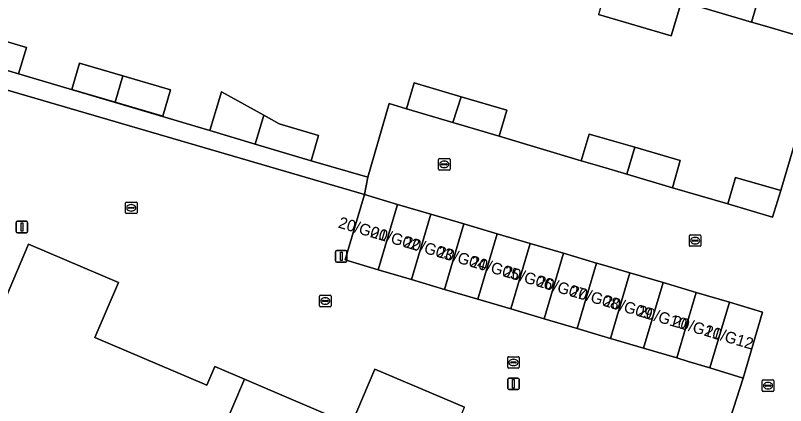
# Model space of a CAD drawing. Extents: x 161771 to 163125, y 382475 to 383179.
# Drawn here: x 162448.9 to 162516.2, y 382553 to 382587.1 of the extents above; entities that cross this region are included whole.
import ezdxf

# ---------------------------------------------------------------- set-up
doc = ezdxf.new("R2010")
doc.units = 0
for name, color, linetype in [('IMGEO_Erf', 7, 'Continuous'), ('IMGEO_Kolk', 7, 'Continuous'), ('IMGEO_Lichtmast', 7, 'Continuous'), ('IMGEO_Pand', 7, 'Continuous'), ('IMGEO_Pand_nummerreeks', 7, 'Continuous'), ('IMGEO_Voetpad_open', 7, 'Continuous')]:
    doc.layers.add(name, color=color, linetype=linetype)

msp = doc.modelspace()

# ---------------------------------------------------------------- linework, layer by layer
at = {"layer": 'IMGEO_Erf'}
for points in [[(162445.786, 382585.524), (162449.901, 382584.31), (162449.219, 382581.999), (162465.935, 382577.029), (162466.944, 382580.427), (162470.647, 382578.383), (162472.001, 382577.636), (162475.434, 382576.617), (162474.776, 382574.402), (162479.73, 382572.971), (162481.59, 382579.408), (162483.122, 382578.939), (162483.791, 382581.207), (162487.9, 382579.994), (162491.899, 382578.814), (162491.23, 382576.546), (162498.393, 382574.396), (162499.085, 382576.732), (162500, 382576.466), (162503.067, 382575.574), (162507.047, 382574.417), (162506.373, 382572.017), (162511.188, 382570.626), (162511.868, 382572.919), (162515.824, 382571.805), (162519.617, 382584.659), (162514.821, 382586.07), (162513.27, 382586.527), (162507.137, 382588.332), (162506.251, 382585.323), (162499.891, 382587.195)], [(162498.043, 382559.715), (162495.145, 382560.573), (162492.246, 382561.431), (162489.348, 382562.289), (162486.449, 382563.147), (162483.551, 382564.005), (162480.652, 382564.863), (162477.755, 382565.721), (162478.027, 382566.642), (162479.442, 382571.437), (162443.542, 382581.946)], [(162448.082, 382562.355), (162450.099, 382567.09), (162457.939, 382563.752), (162455.89, 382558.94), (162465.676, 382554.773), (162466.362, 382556.385), (162468.969, 382555.275), (162478.286, 382551.307), (162480.358, 382556.171), (162483.588, 382554.796), (162488.188, 382552.837)], [(162496.909, 382530.58), (162500, 382530.088), (162505.054, 382529.284), (162508.84, 382542.177), (162510.869, 382549.086), (162510.567, 382549.224), (162512.541, 382555.383), (162509.637, 382556.284), (162507.741, 382556.844), (162506.738, 382557.141), (162503.84, 382557.999), (162500.942, 382558.857), (162500.167, 382559.086), (162498.043, 382559.715)]]:
    msp.add_lwpolyline(points, dxfattribs=at)
msp.add_lwpolyline([(162461.814, 382578.283), (162457.649, 382579.512), (162453.863, 382580.629), (162454.545, 382582.94), (162458.331, 382581.822), (162462.495, 382580.593)], close=True, dxfattribs=at)
at = {"layer": 'IMGEO_Kolk'}
for p, q in [((162485.92, 382573.655), (162485.92, 382574.507)), ((162485.995, 382574.581), (162486.847, 382574.581)), ((162486.408, 382574.361), (162486.433, 382574.361)), ((162486.921, 382574.507), (162486.921, 382573.655)), ((162486.847, 382573.581), (162485.995, 382573.581)), ((162486.179, 382574.075), (162486.179, 382574.087)), ((162486.617, 382574.038), (162486.219, 382574.038)), ((162486.222, 382574.124), (162486.62, 382574.124)), ((162486.431, 382573.801), (162486.406, 382573.801)), ((162486.663, 382574.087), (162486.663, 382574.075)), ((162458.569, 382569.851), (162458.569, 382570.703)), ((162458.644, 382570.777), (162459.496, 382570.777)), ((162458.828, 382570.271), (162458.828, 382570.283)), ((162459.266, 382570.234), (162458.868, 382570.234)), ((162458.871, 382570.32), (162459.269, 382570.32)), ((162459.057, 382570.557), (162459.082, 382570.557)), ((162459.312, 382570.283), (162459.312, 382570.271)), ((162459.57, 382570.703), (162459.57, 382569.851)), ((162459.496, 382569.777), (162458.644, 382569.777)), ((162459.08, 382569.997), (162459.055, 382569.997)), ((162507.84, 382566.985), (162507.84, 382567.837)), ((162507.915, 382567.911), (162508.767, 382567.911)), ((162508.142, 382567.454), (162508.54, 382567.454)), ((162508.328, 382567.691), (162508.353, 382567.691)), ((162508.841, 382567.837), (162508.841, 382566.985)), ((162508.767, 382566.911), (162507.915, 382566.911)), ((162508.099, 382567.405), (162508.099, 382567.417)), ((162508.537, 382567.368), (162508.139, 382567.368)), ((162508.351, 382567.131), (162508.326, 382567.131)), ((162508.583, 382567.417), (162508.583, 382567.405)), ((162475.522, 382561.705), (162475.522, 382562.557)), ((162475.597, 382562.631), (162476.449, 382562.631)), ((162475.781, 382562.125), (162475.781, 382562.137)), ((162476.219, 382562.088), (162475.821, 382562.088)), ((162475.824, 382562.174), (162476.222, 382562.174)), ((162476.01, 382562.411), (162476.035, 382562.411)), ((162476.265, 382562.137), (162476.265, 382562.125)), ((162476.523, 382562.557), (162476.523, 382561.705)), ((162476.449, 382561.631), (162475.597, 382561.631)), ((162476.033, 382561.851), (162476.008, 382561.851)), ((162491.962, 382556.324), (162491.962, 382557.176)), ((162492.037, 382557.25), (162492.889, 382557.25)), ((162492.221, 382556.744), (162492.221, 382556.756)), ((162492.659, 382556.707), (162492.261, 382556.707)), ((162492.264, 382556.793), (162492.662, 382556.793)), ((162492.45, 382557.03), (162492.475, 382557.03)), ((162492.705, 382556.756), (162492.705, 382556.744)), ((162492.963, 382557.176), (162492.963, 382556.324)), ((162492.889, 382556.25), (162492.037, 382556.25)), ((162492.473, 382556.47), (162492.448, 382556.47)), ((162514.209, 382554.295), (162514.209, 382555.147)), ((162514.284, 382555.221), (162515.136, 382555.221)), ((162514.468, 382554.715), (162514.468, 382554.727)), ((162514.906, 382554.678), (162514.508, 382554.678)), ((162514.511, 382554.764), (162514.909, 382554.764)), ((162514.697, 382555.001), (162514.722, 382555.001)), ((162514.952, 382554.727), (162514.952, 382554.715)), ((162515.21, 382555.147), (162515.21, 382554.295)), ((162515.136, 382554.221), (162514.284, 382554.221)), ((162514.72, 382554.441), (162514.695, 382554.441))]:
    msp.add_line(p, q, dxfattribs=at)
for points in [[(162485.92, 382573.655), (162485.92, 382574.507)], [(162485.995, 382574.581), (162486.847, 382574.581)], [(162486.921, 382574.507), (162486.921, 382573.655)], [(162486.847, 382573.581), (162485.995, 382573.581)], [(162458.569, 382569.851), (162458.569, 382570.703)], [(162458.644, 382570.777), (162459.496, 382570.777)], [(162459.57, 382570.703), (162459.57, 382569.851)], [(162459.496, 382569.777), (162458.644, 382569.777)], [(162507.84, 382566.985), (162507.84, 382567.837)], [(162507.915, 382567.911), (162508.767, 382567.911)], [(162508.841, 382567.837), (162508.841, 382566.985)], [(162508.767, 382566.911), (162507.915, 382566.911)], [(162475.522, 382561.705), (162475.522, 382562.557)], [(162475.597, 382562.631), (162476.449, 382562.631)], [(162476.523, 382562.557), (162476.523, 382561.705)], [(162476.449, 382561.631), (162475.597, 382561.631)], [(162491.962, 382556.324), (162491.962, 382557.176)], [(162492.037, 382557.25), (162492.889, 382557.25)], [(162492.963, 382557.176), (162492.963, 382556.324)], [(162492.889, 382556.25), (162492.037, 382556.25)], [(162514.209, 382554.295), (162514.209, 382555.147)], [(162514.284, 382555.221), (162515.136, 382555.221)], [(162515.21, 382555.147), (162515.21, 382554.295)], [(162515.136, 382554.221), (162514.284, 382554.221)]]:
    msp.add_lwpolyline(points, dxfattribs=at)
for centre, radius, start, end in [((162485.997, 382574.505), 0.0765, 91.55205, 178.44795), ((162485.997, 382574.505), 0.0765, 91.55205, 178.44795), ((162486.845, 382574.505), 0.0765, 1.55205, 88.44795), ((162486.845, 382574.505), 0.0765, 1.55205, 88.44795), ((162485.997, 382573.657), 0.0765, 181.55205, 268.44795), ((162485.997, 382573.657), 0.0765, 181.55205, 268.44795), ((162486.219, 382574.084), 0.0403, 85.87752, 175.75265), ((162486.216, 382574.074), 0.0366, 178.93798, 274.71019), ((162486.62, 382574.081), 0.043, 264.86636, 352.45326), ((162486.624, 382574.086), 0.0386, 1.73085, 96.63898), ((162486.845, 382573.657), 0.0765, 271.55205, 358.44795), ((162486.845, 382573.657), 0.0765, 271.55205, 358.44795), ((162458.646, 382570.701), 0.0765, 91.55205, 178.44795), ((162458.646, 382570.701), 0.0765, 91.55205, 178.44795), ((162458.868, 382570.28), 0.0403, 85.87752, 175.75265), ((162458.865, 382570.27), 0.0366, 178.93798, 274.71019), ((162459.269, 382570.277), 0.043, 264.86636, 352.45326), ((162459.273, 382570.282), 0.0386, 1.73085, 96.63898), ((162459.494, 382570.701), 0.0765, 1.55205, 88.44795), ((162459.494, 382570.701), 0.0765, 1.55205, 88.44795), ((162458.646, 382569.853), 0.0765, 181.55205, 268.44795), ((162458.646, 382569.853), 0.0765, 181.55205, 268.44795), ((162459.494, 382569.853), 0.0765, 271.55205, 358.44795), ((162459.494, 382569.853), 0.0765, 271.55205, 358.44795), ((162507.917, 382567.835), 0.0765, 91.55205, 178.44795), ((162507.917, 382567.835), 0.0765, 91.55205, 178.44795), ((162508.139, 382567.414), 0.0403, 85.87752, 175.75265), ((162508.544, 382567.416), 0.0386, 1.73085, 96.63898), ((162508.765, 382567.835), 0.0765, 1.55205, 88.44795), ((162508.765, 382567.835), 0.0765, 1.55205, 88.44795), ((162507.917, 382566.987), 0.0765, 181.55205, 268.44795), ((162507.917, 382566.987), 0.0765, 181.55205, 268.44795), ((162508.136, 382567.404), 0.0366, 178.93798, 274.71019), ((162508.54, 382567.411), 0.043, 264.86636, 352.45326), ((162508.765, 382566.987), 0.0765, 271.55205, 358.44795), ((162508.765, 382566.987), 0.0765, 271.55205, 358.44795), ((162475.599, 382562.555), 0.0765, 91.55205, 178.44795), ((162475.599, 382562.555), 0.0765, 91.55205, 178.44795), ((162475.821, 382562.134), 0.0403, 85.87752, 175.75265), ((162475.818, 382562.124), 0.0366, 178.93798, 274.71019), ((162476.222, 382562.131), 0.043, 264.86636, 352.45326), ((162476.226, 382562.136), 0.0386, 1.73085, 96.63898), ((162476.447, 382562.555), 0.0765, 1.55205, 88.44795), ((162476.447, 382562.555), 0.0765, 1.55205, 88.44795), ((162475.599, 382561.707), 0.0765, 181.55205, 268.44795), ((162475.599, 382561.707), 0.0765, 181.55205, 268.44795), ((162476.447, 382561.707), 0.0765, 271.55205, 358.44795), ((162476.447, 382561.707), 0.0765, 271.55205, 358.44795), ((162492.039, 382557.174), 0.0765, 91.55205, 178.44795), ((162492.039, 382557.174), 0.0765, 91.55205, 178.44795), ((162492.261, 382556.753), 0.0403, 85.87752, 175.75265), ((162492.258, 382556.743), 0.0366, 178.93798, 274.71019), ((162492.662, 382556.75), 0.043, 264.86636, 352.45326), ((162492.666, 382556.755), 0.0386, 1.73085, 96.63898), ((162492.887, 382557.174), 0.0765, 1.55205, 88.44795), ((162492.887, 382557.174), 0.0765, 1.55205, 88.44795), ((162492.039, 382556.326), 0.0765, 181.55205, 268.44795), ((162492.039, 382556.326), 0.0765, 181.55205, 268.44795), ((162492.887, 382556.326), 0.0765, 271.55205, 358.44795), ((162492.887, 382556.326), 0.0765, 271.55205, 358.44795), ((162514.286, 382555.145), 0.0765, 91.55205, 178.44795), ((162514.286, 382555.145), 0.0765, 91.55205, 178.44795), ((162514.508, 382554.724), 0.0403, 85.87752, 175.75265), ((162514.505, 382554.714), 0.0366, 178.93798, 274.71019), ((162514.909, 382554.721), 0.043, 264.86636, 352.45326), ((162514.913, 382554.726), 0.0386, 1.73085, 96.63898), ((162515.134, 382555.145), 0.0765, 1.55205, 88.44795), ((162515.134, 382555.145), 0.0765, 1.55205, 88.44795), ((162514.286, 382554.297), 0.0765, 181.55205, 268.44795), ((162514.286, 382554.297), 0.0765, 181.55205, 268.44795), ((162515.134, 382554.297), 0.0765, 271.55205, 358.44795), ((162515.134, 382554.297), 0.0765, 271.55205, 358.44795)]:
    msp.add_arc(centre, radius, start, end, dxfattribs=at)
for centre, major_axis, ratio, start_param, end_param in [((162486.407, 382574.081), (-0.387, 0.002), 0.722429, 4.712389, 7.853982), ((162486.432, 382574.081), (-0.39, 0.002), 0.717154, 1.570796, 4.712389), ((162459.056, 382570.277), (-0.387, 0.002), 0.722429, 4.712389, 7.853982), ((162459.081, 382570.277), (-0.39, 0.002), 0.717154, 1.570796, 4.712389), ((162508.327, 382567.411), (-0.387, 0.002), 0.722429, 4.712389, 7.853982), ((162508.352, 382567.411), (-0.39, 0.002), 0.717154, 1.570796, 4.712389), ((162476.009, 382562.131), (-0.387, 0.002), 0.722429, 4.712389, 7.853982), ((162476.034, 382562.131), (-0.39, 0.002), 0.717154, 1.570796, 4.712389), ((162492.449, 382556.75), (-0.387, 0.002), 0.722429, 4.712389, 7.853982), ((162492.474, 382556.75), (-0.39, 0.002), 0.717154, 1.570796, 4.712389), ((162514.696, 382554.721), (-0.387, 0.002), 0.722429, 4.712389, 7.853982), ((162514.721, 382554.721), (-0.39, 0.002), 0.717154, 1.570796, 4.712389)]:
    msp.add_ellipse(centre, major_axis=major_axis, ratio=ratio, start_param=start_param, end_param=end_param, dxfattribs=at)
at = {"layer": 'IMGEO_Lichtmast'}
for p, q in [((162449.021, 382568.203), (162449.021, 382569.003)), ((162449.021, 382569.003), (162449.021, 382568.203)), ((162449.121, 382569.103), (162449.911, 382569.103)), ((162449.911, 382569.103), (162449.121, 382569.103)), ((162450.011, 382569.003), (162450.011, 382568.203)), ((162450.011, 382568.203), (162450.011, 382569.003)), ((162449.911, 382568.103), (162449.121, 382568.103)), ((162449.121, 382568.103), (162449.911, 382568.103)), ((162476.918, 382565.638), (162476.918, 382566.438)), ((162476.918, 382566.438), (162476.918, 382565.638)), ((162477.018, 382566.538), (162477.808, 382566.538)), ((162477.808, 382566.538), (162477.018, 382566.538)), ((162477.908, 382566.438), (162477.908, 382565.638)), ((162477.908, 382565.638), (162477.908, 382566.438)), ((162477.808, 382565.538), (162477.018, 382565.538)), ((162477.018, 382565.538), (162477.808, 382565.538)), ((162492.07, 382555.384), (162492.86, 382555.384)), ((162492.86, 382555.384), (162492.07, 382555.384)), ((162491.97, 382554.484), (162491.97, 382555.284)), ((162491.97, 382555.284), (162491.97, 382554.484)), ((162492.96, 382555.284), (162492.96, 382554.484)), ((162492.96, 382554.484), (162492.96, 382555.284)), ((162492.86, 382554.384), (162492.07, 382554.384)), ((162492.07, 382554.384), (162492.86, 382554.384))]:
    msp.add_line(p, q, dxfattribs=at)
for points in [[(162449.441, 382568.978), (162449.591, 382568.978), (162449.591, 382568.228), (162449.441, 382568.228), (162449.441, 382568.978)], [(162477.338, 382566.413), (162477.488, 382566.413), (162477.488, 382565.663), (162477.338, 382565.663), (162477.338, 382566.413)], [(162492.39, 382555.259), (162492.54, 382555.259), (162492.54, 382554.509), (162492.39, 382554.509), (162492.39, 382555.259)]]:
    msp.add_lwpolyline(points, dxfattribs=at)
for centre, start, end in [((162449.121, 382569.003), 90, 180), ((162449.121, 382569.003), 90, 180), ((162449.911, 382569.003), 0, 90), ((162449.911, 382569.003), 360, 90), ((162449.121, 382568.203), 180, 270), ((162449.121, 382568.203), 180, 270), ((162449.911, 382568.203), 270, 0), ((162449.911, 382568.203), 270, 0), ((162477.018, 382566.438), 90, 180), ((162477.018, 382566.438), 90, 180), ((162477.808, 382566.438), 0, 90), ((162477.808, 382566.438), 360, 90), ((162477.018, 382565.638), 180, 270), ((162477.018, 382565.638), 180, 270), ((162477.808, 382565.638), 270, 0), ((162477.808, 382565.638), 270, 0), ((162492.07, 382555.284), 90, 180), ((162492.07, 382555.284), 90, 180), ((162492.86, 382555.284), 0, 90), ((162492.86, 382555.284), 360, 90), ((162492.07, 382554.484), 180, 270), ((162492.07, 382554.484), 180, 270), ((162492.86, 382554.484), 270, 0), ((162492.86, 382554.484), 270, 0)]:
    msp.add_arc(centre, 0.1, start, end, dxfattribs=at)
at = {"layer": 'IMGEO_Pand'}
for points in [[(162509.409, 382596.447), (162505.916, 382597.477), (162505.828, 382597.177), (162503.068, 382597.989), (162500.748, 382590.213), (162499.972, 382587.47), (162499.891, 382587.195), (162506.251, 382585.323), (162507.137, 382588.332), (162507.032, 382588.363)], [(162515.548, 382594.26), (162512.798, 382595.069), (162512.898, 382595.414), (162509.409, 382596.447), (162507.032, 382588.363), (162507.137, 382588.332), (162513.27, 382586.527)], [(162521.99, 382592.721), (162518.398, 382593.785), (162518.3, 382593.45), (162515.548, 382594.26), (162513.27, 382586.527), (162514.821, 382586.07), (162519.617, 382584.659)], [(162449.901, 382584.31), (162445.786, 382585.524), (162445.105, 382583.214), (162449.219, 382581.999)], [(162458.331, 382581.822), (162454.545, 382582.94), (162453.863, 382580.629), (162457.649, 382579.512)], [(162458.331, 382581.822), (162457.649, 382579.512), (162461.814, 382578.283), (162462.495, 382580.593)], [(162487.173, 382577.743), (162487.9, 382579.994), (162483.791, 382581.207), (162483.122, 382578.939)], [(162470.647, 382578.383), (162466.944, 382580.427), (162465.935, 382577.029), (162469.898, 382575.851)], [(162487.173, 382577.743), (162491.23, 382576.546), (162491.899, 382578.814), (162487.9, 382579.994)], [(162470.647, 382578.383), (162469.898, 382575.851), (162474.776, 382574.402), (162475.434, 382576.617), (162472.001, 382577.636)], [(162503.067, 382575.574), (162500, 382576.466), (162499.085, 382576.732), (162498.393, 382574.396), (162500, 382573.917), (162502.372, 382573.21)], [(162503.067, 382575.574), (162502.372, 382573.21), (162506.373, 382572.017), (162507.047, 382574.417)], [(162515.824, 382571.805), (162511.868, 382572.919), (162511.188, 382570.626), (162515.105, 382569.472)], [(162482.341, 382570.581), (162479.442, 382571.437), (162478.027, 382566.642), (162477.755, 382565.721), (162480.652, 382564.863)], [(162485.24, 382569.725), (162482.341, 382570.581), (162480.652, 382564.863), (162483.551, 382564.005)], [(162488.139, 382568.868), (162485.24, 382569.725), (162483.551, 382564.005), (162486.449, 382563.147)], [(162491.038, 382568.012), (162488.139, 382568.868), (162486.449, 382563.147), (162489.348, 382562.289)], [(162455.89, 382558.94), (162457.939, 382563.752), (162450.099, 382567.09), (162448.082, 382562.355), (162433.486, 382568.571), (162431.057, 382562.867), (162429.486, 382559.177), (162428.378, 382556.576), (162442.176, 382550.686), (162456.309, 382544.653), (162459.282, 382543.394), (162459.996, 382544.99), (162463.859, 382543.342), (162468.969, 382555.275), (162466.362, 382556.385), (162465.676, 382554.773)], [(162493.937, 382567.156), (162491.038, 382568.012), (162489.348, 382562.289), (162492.246, 382561.431)], [(162496.836, 382566.3), (162493.937, 382567.156), (162492.246, 382561.431), (162495.145, 382560.573)], [(162499.735, 382565.444), (162496.836, 382566.3), (162495.145, 382560.573), (162498.043, 382559.715)], [(162502.634, 382564.587), (162500.167, 382565.316), (162499.735, 382565.444), (162498.043, 382559.715), (162500.167, 382559.086), (162500.942, 382558.857)], [(162505.533, 382563.731), (162502.634, 382564.587), (162500.942, 382558.857), (162503.84, 382557.999)], [(162508.432, 382562.875), (162505.533, 382563.731), (162503.84, 382557.999), (162506.738, 382557.141)], [(162511.331, 382562.018), (162508.432, 382562.875), (162506.738, 382557.141), (162507.741, 382556.844), (162509.637, 382556.284)], [(162514.23, 382561.162), (162511.331, 382562.018), (162509.637, 382556.284), (162512.541, 382555.383)], [(162487.561, 382551.364), (162488.188, 382552.837), (162483.588, 382554.796), (162480.358, 382556.171), (162478.286, 382551.307), (162468.969, 382555.275), (162463.859, 382543.342), (162479.345, 382536.736), (162480.038, 382538.321), (162484.309, 382536.517), (162484.994, 382538.139), (162498.39, 382532.406), (162499.067, 382534.004), (162502.196, 382532.679), (162502.883, 382534.282), (162505.539, 382533.532), (162508.291, 382542.509)]]:
    msp.add_lwpolyline(points, close=True, dxfattribs=at)
at = {"layer": 'IMGEO_Voetpad_open'}
msp.add_lwpolyline([(162450.808, 382602.815), (162451.781, 382606.114), (162453.196, 382610.909), (162455.048, 382617.15), (162453.051, 382617.743), (162452.021, 382613.36), (162447.736, 382599.329), (162447.021, 382596.856), (162446.694, 382595.726), (162447.462, 382595.504), (162443.542, 382581.946), (162479.442, 382571.437), (162479.73, 382572.971), (162474.776, 382574.402), (162469.898, 382575.851), (162465.935, 382577.029), (162449.219, 382581.999), (162445.105, 382583.214), (162445, 382583.251), (162449.807, 382599.423)], close=True, dxfattribs=at)
msp.add_lwpolyline([(162519.617, 382584.659), (162515.824, 382571.805), (162515.105, 382569.472), (162511.188, 382570.626), (162506.373, 382572.017), (162502.372, 382573.21), (162500, 382573.917), (162498.393, 382574.396), (162491.23, 382576.546), (162487.173, 382577.743), (162483.122, 382578.939), (162481.59, 382579.408), (162479.73, 382572.971), (162479.442, 382571.437), (162482.341, 382570.581), (162485.24, 382569.725), (162488.139, 382568.868), (162491.038, 382568.012), (162493.937, 382567.156), (162496.836, 382566.3), (162499.735, 382565.444), (162500.167, 382565.316), (162502.634, 382564.587), (162505.533, 382563.731), (162508.432, 382562.875), (162511.331, 382562.018), (162514.23, 382561.162), (162512.541, 382555.383), (162510.567, 382549.224)], dxfattribs=at)

# ---------------------------------------------------------------- texts
at = {"layer": 'IMGEO_Pand_nummerreeks'}
for s, p in [('20/G01', (162477.09, 382568.562)), ('20/G02', (162479.886, 382567.736)), ('20/G03', (162482.8, 382566.875)), ('20/G04', (162485.708, 382566.015)), ('20/G05', (162488.616, 382565.156)), ('20/G06', (162491.524, 382564.297)), ('20/G07', (162494.432, 382563.437)), ('20/G08', (162497.343, 382562.577)), ('20/G09', (162500.245, 382561.719)), ('20/G10', (162503.247, 382560.832)), ('20/G11', (162506.258, 382559.943)), ('20/G12', (162509.054, 382559.116))]:
    msp.add_text(s, height=1, rotation=343.53892, dxfattribs=at).set_placement(p)

doc.saveas('drawing.dxf')
